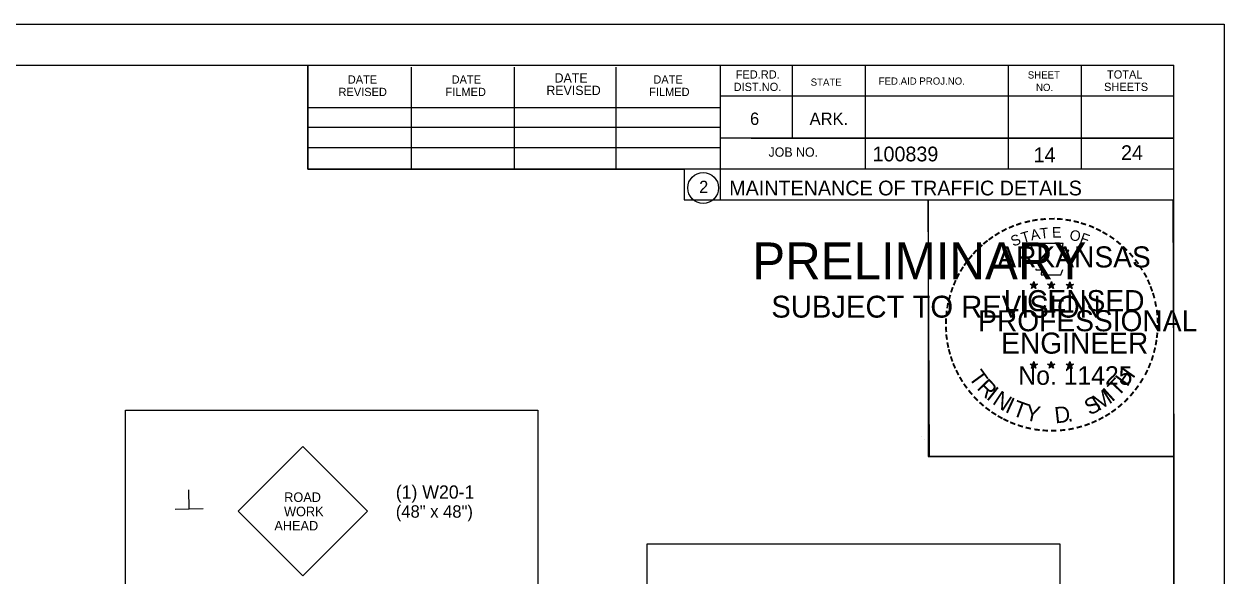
# Model space of a CAD drawing. Extents: x 9792 to 14027, y 9583 to 10649.
# Drawn here: x 10889 to 11459, y 10387 to 10649 of the extents above; entities that cross this region are included whole.
import ezdxf

# ---------------------------------------------------------------- set-up
doc = ezdxf.new("R2010")
doc.units = 0
for name, color, linetype in [('Default', 7, 'Continuous'), ('R_Border', 7, 'Continuous'), ('R_Border Notes', 7, 'Continuous'), ('R_Border PE', 7, 'Continuous'), ('R_Border Prem', 7, 'Continuous'), ('R_Draft', 7, 'Continuous'), ('R_No Plot', 7, 'Continuous')]:
    doc.layers.add(name, color=color, linetype=linetype)

msp = doc.modelspace()

# ---------------------------------------------------------------- linework, layer by layer
at = {"layer": 'Default'}
for p, q in [((11021.52, 10448.84), (10990.87, 10418.19)), ((11052.17, 10418.19), (11021.52, 10448.84)), ((10967.6, 10419.31), (10967.45, 10428.34)), ((10974.19, 10419.23), (10960.95, 10419.01)), ((11021.52, 10387.56), (10990.87, 10418.19)), ((11052.17, 10418.19), (11021.52, 10387.56))]:
    msp.add_line(p, q, dxfattribs=at)
at = {"layer": 'R_Border'}
for p, q in [((9854.26, 10629.85), (11435.16, 10629.85)), ((11023.86, 10580.45), (11023.86, 10629.85)), ((11073.16, 10580.45), (11073.16, 10628.85)), ((11121.96, 10580.45), (11121.96, 10628.85)), ((11170.36, 10580.45), (11170.36, 10628.85)), ((11219.66, 10629.85), (11219.66, 10565.85)), ((11253.86, 10629.85), (11253.86, 10595.15)), ((11288.56, 10629.85), (11288.56, 10580.45)), ((11356.46, 10629.85), (11356.46, 10580.45)), ((11391.16, 10629.85), (11391.16, 10580.45)), ((11435.16, 9602.55), (11435.16, 10629.85)), ((11435.16, 10615.15), (11219.66, 10615.15)), ((11435.16, 10615.25), (11435.16, 10615.25)), ((11023.86, 10609.75), (11219.66, 10609.75)), ((11023.86, 10600.45), (11219.66, 10600.45)), ((11435.16, 10595.15), (11219.66, 10595.15)), ((11234.46, 10595.15), (11435.16, 10595.15)), ((11023.86, 10580.45), (11023.86, 10590.75)), ((11023.86, 10590.75), (11219.66, 10590.75)), ((11435.16, 10580.45), (11023.86, 10580.45)), ((11219.66, 10565.85), (11435.16, 10565.85))]:
    msp.add_line(p, q, dxfattribs=at)
msp.add_circle((11211.6, 10571.53), 7.33, dxfattribs=at)
at = {"layer": 'R_Border Notes'}
for points in [[(10937.26, 10466.18), (11133.09, 10466.18), (11133.09, 10231.02), (10937.26, 10231.02)], [(11185.08, 10402.65), (11380.91, 10402.65), (11380.91, 10252.35), (11185.08, 10252.35)]]:
    msp.add_lwpolyline(points, close=True, dxfattribs=at)
at = {"layer": 'R_Border PE'}
for p, q in [((11366.84, 10525.86), (11368.59, 10525.31)), ((11366.84, 10525.86), (11368.11, 10525.64)), ((11366.84, 10525.86), (11368.03, 10525.25)), ((11367.51, 10523.82), (11368.59, 10525.31)), ((11367.51, 10523.82), (11368.14, 10525.04)), ((11367.51, 10523.82), (11368.58, 10524.91)), ((11368.59, 10527.13), (11368.38, 10525.87)), ((11369.65, 10523.82), (11368.58, 10524.89)), ((11368.59, 10525.31), (11368.59, 10527.13)), ((11368.59, 10527.13), (11368.83, 10525.88)), ((11370.32, 10525.86), (11368.59, 10525.31)), ((11369.65, 10523.82), (11368.59, 10525.31)), ((11370.32, 10525.86), (11368.89, 10525.62)), ((11369.65, 10523.82), (11368.97, 10525.28)), ((11370.32, 10525.86), (11369.3, 10525.35)), ((11375.19, 10525.86), (11376.94, 10525.31)), ((11375.19, 10525.86), (11376.46, 10525.64)), ((11375.19, 10525.86), (11376.38, 10525.25)), ((11375.86, 10523.82), (11376.94, 10525.31)), ((11375.86, 10523.82), (11376.49, 10525.04)), ((11375.86, 10523.82), (11376.93, 10524.91)), ((11376.94, 10527.13), (11376.73, 10525.87)), ((11378, 10523.82), (11376.93, 10524.89)), ((11376.94, 10525.31), (11376.94, 10527.13)), ((11376.94, 10527.13), (11377.18, 10525.88)), ((11378.67, 10525.86), (11376.94, 10525.31)), ((11378, 10523.82), (11376.94, 10525.31)), ((11378.67, 10525.86), (11377.24, 10525.62)), ((11378, 10523.82), (11377.32, 10525.28)), ((11378.67, 10525.86), (11377.65, 10525.35)), ((11384.01, 10525.8), (11385.76, 10525.25)), ((11384.01, 10525.8), (11385.28, 10525.58)), ((11384.01, 10525.8), (11385.2, 10525.19)), ((11384.68, 10523.76), (11385.76, 10525.25)), ((11384.68, 10523.76), (11385.31, 10524.98)), ((11384.68, 10523.76), (11385.75, 10524.85)), ((11385.76, 10527.07), (11385.55, 10525.81)), ((11386.82, 10523.76), (11385.75, 10524.83)), ((11385.76, 10525.25), (11385.76, 10527.07)), ((11385.76, 10527.07), (11386, 10525.82)), ((11387.49, 10525.8), (11385.76, 10525.25)), ((11386.82, 10523.76), (11385.76, 10525.25)), ((11387.49, 10525.8), (11386.06, 10525.56)), ((11386.82, 10523.76), (11386.14, 10525.22)), ((11387.49, 10525.8), (11386.47, 10525.29)), ((11366.82, 10488), (11368.57, 10487.44)), ((11366.82, 10488), (11368.09, 10487.77)), ((11366.82, 10488), (11368.01, 10487.39)), ((11367.49, 10485.96), (11368.57, 10487.44)), ((11367.49, 10485.96), (11368.12, 10487.18)), ((11367.49, 10485.96), (11368.56, 10487.04)), ((11368.57, 10489.27), (11368.36, 10488.01)), ((11369.63, 10485.96), (11368.56, 10487.03)), ((11368.57, 10487.44), (11368.57, 10489.27)), ((11368.57, 10489.27), (11368.81, 10488.02)), ((11370.3, 10488), (11368.57, 10487.44)), ((11369.63, 10485.96), (11368.57, 10487.44)), ((11370.3, 10488), (11368.87, 10487.75)), ((11369.63, 10485.96), (11368.95, 10487.41)), ((11370.3, 10488), (11369.28, 10487.49)), ((11375.17, 10488), (11376.91, 10487.44)), ((11375.17, 10488), (11376.43, 10487.77)), ((11375.17, 10488), (11376.35, 10487.39)), ((11375.83, 10485.96), (11376.91, 10487.44)), ((11375.83, 10485.96), (11376.46, 10487.18)), ((11375.83, 10485.96), (11376.9, 10487.04)), ((11376.91, 10489.27), (11376.71, 10488.01)), ((11377.98, 10485.96), (11376.9, 10487.03)), ((11376.91, 10487.44), (11376.91, 10489.27)), ((11376.91, 10489.27), (11377.16, 10488.02)), ((11378.65, 10488), (11376.91, 10487.44)), ((11377.98, 10485.96), (11376.91, 10487.44)), ((11378.65, 10488), (11377.22, 10487.75)), ((11377.98, 10485.96), (11377.29, 10487.41)), ((11378.65, 10488), (11377.63, 10487.49)), ((11384, 10487.95), (11385.75, 10487.39)), ((11384, 10487.95), (11385.27, 10487.72)), ((11384, 10487.95), (11385.19, 10487.34)), ((11384.67, 10485.91), (11385.75, 10487.39)), ((11384.67, 10485.91), (11385.3, 10487.13)), ((11384.67, 10485.91), (11385.74, 10486.99)), ((11385.75, 10489.22), (11385.54, 10487.96)), ((11386.81, 10485.91), (11385.74, 10486.98)), ((11385.75, 10487.39), (11385.75, 10489.22)), ((11385.75, 10489.22), (11385.99, 10487.97)), ((11387.48, 10487.95), (11385.75, 10487.39)), ((11386.81, 10485.91), (11385.75, 10487.39)), ((11387.48, 10487.95), (11386.05, 10487.7)), ((11386.81, 10485.91), (11386.13, 10487.36)), ((11387.48, 10487.95), (11386.46, 10487.44))]:
    msp.add_line(p, q, dxfattribs=at)
for points in [[(11367.05, 10545.25), (11368.39, 10541.12)], [(11384.6, 10540.64), (11385.31, 10542.06), (11381.89, 10541.94), (11382.63, 10545.25), (11367.05, 10545.25)], [(11369.51, 10533.14), (11369.51, 10532.7), (11372.32, 10532.61), (11372.05, 10530.24), (11381.4, 10530.24), (11382.41, 10532.92)], [(11368.59, 10527.13), (11369.65, 10523.82), (11366.84, 10525.86), (11370.32, 10525.86), (11367.51, 10523.82), (11368.59, 10527.13)], [(11376.94, 10527.13), (11378, 10523.82), (11375.19, 10525.86), (11378.67, 10525.86), (11375.86, 10523.82), (11376.94, 10527.13)], [(11385.76, 10527.07), (11386.82, 10523.76), (11384.01, 10525.8), (11387.49, 10525.8), (11384.68, 10523.76), (11385.76, 10527.07)], [(11368.57, 10489.27), (11369.63, 10485.96), (11366.82, 10488), (11370.3, 10488), (11367.49, 10485.96), (11368.57, 10489.27)], [(11376.91, 10489.27), (11377.98, 10485.96), (11375.17, 10488), (11378.65, 10488), (11375.83, 10485.96), (11376.91, 10489.27)], [(11385.75, 10489.22), (11386.81, 10485.91), (11384, 10487.95), (11387.48, 10487.95), (11384.67, 10485.91), (11385.75, 10489.22)]]:
    msp.add_lwpolyline(points, dxfattribs=at)
for centre, radius in [((11368.58, 10525.31), 0.861), ((11368.58, 10525.31), 0.723), ((11368.58, 10525.31), 0.579), ((11368.58, 10525.31), 0.495), ((11368.58, 10525.31), 0.374), ((11368.58, 10525.31), 0.248), ((11368.58, 10525.31), 0.148), ((11376.93, 10525.31), 0.861), ((11376.93, 10525.31), 0.723), ((11376.93, 10525.31), 0.579), ((11376.93, 10525.31), 0.495), ((11376.93, 10525.31), 0.374), ((11376.93, 10525.31), 0.248), ((11376.93, 10525.31), 0.148), ((11385.75, 10525.25), 0.861), ((11385.75, 10525.25), 0.723), ((11385.75, 10525.25), 0.579), ((11385.75, 10525.25), 0.495), ((11385.75, 10525.25), 0.374), ((11385.75, 10525.25), 0.248), ((11385.75, 10525.25), 0.148), ((11368.56, 10487.44), 0.861), ((11368.56, 10487.44), 0.723), ((11368.56, 10487.44), 0.579), ((11368.56, 10487.44), 0.495), ((11368.56, 10487.44), 0.374), ((11368.56, 10487.44), 0.248), ((11368.56, 10487.44), 0.148), ((11376.91, 10487.44), 0.861), ((11376.91, 10487.44), 0.723), ((11376.91, 10487.44), 0.579), ((11376.91, 10487.44), 0.495), ((11376.91, 10487.44), 0.374), ((11376.91, 10487.44), 0.248), ((11376.91, 10487.44), 0.148), ((11385.74, 10487.39), 0.861), ((11385.74, 10487.39), 0.723), ((11385.74, 10487.39), 0.579), ((11385.74, 10487.39), 0.495), ((11385.74, 10487.39), 0.374), ((11385.74, 10487.39), 0.248), ((11385.74, 10487.39), 0.148)]:
    msp.add_circle(centre, radius, dxfattribs=at)
at = {"layer": 'R_No Plot'}
for p, q in [((9792.26, 10649.32), (11458.93, 10649.32)), ((11315.33, 10453.57), (11315.33, 10453.57)), ((11316.59, 10452.31), (11316.59, 10452.31))]:
    msp.add_line(p, q, dxfattribs=at)
for points in [[(9792.23, 10649.32), (11458.93, 10649.32), (11458.93, 9582.63), (9792.23, 9582.63)], [(11023.86, 10629.85), (11023.86, 10580.45), (11202.52, 10580.45), (11202.52, 10565.85), (11318.52, 10565.85), (11318.52, 10444.19), (11435.16, 10444.19), (11435.16, 9602.55), (9854.26, 9602.55), (9854.26, 10629.85)], [(11318.52, 10565.85), (11434.56, 10565.85), (11435.16, 10444.19), (11319.12, 10444.19)]]:
    msp.add_lwpolyline(points, close=True, dxfattribs=at)

# ---------------------------------------------------------------- texts
at = {"layer": 'Default'}
for s, height, p in [('(1) W20-1', 6.273, (11065.66, 10424.12)), ('(48" x 48")', 5.88, (11065.66, 10415.09))]:
    msp.add_text(s, height=height, dxfattribs=at).set_placement(p)
for s, height, rotation, p in [('ROAD', 4.516, 0.0004, (11012.67, 10422.56)), ('WORK', 4.515, 0, (11012.58, 10415.78)), (' AHEAD ', 4.516, 0.0006, (11006.32, 10409.01))]:
    msp.add_text(s, height=height, rotation=rotation, dxfattribs=at).set_placement(p)
at = {"layer": 'R_Border'}
for s, height, p in [('FED.RD.', 3.91, (11227.06, 10623.45)), ('TOTAL', 3.91, (11403.36, 10623.45)), ('DATE', 3.91, (11042.86, 10621.05)), ('DATE', 3.91, (11092.16, 10621.05)), ('DATE', 4.396, (11141.06, 10621.55)), ('DATE', 3.91, (11187.96, 10621.05)), ('DIST.NO.', 3.91, (11226.06, 10617.55)), ('STATE', 3.42, (11262.66, 10620.05)), ('FED.AID PROJ.NO.', 3.42, (11294.96, 10620.55)), ('SHEET', 3.42, (11365.76, 10623.45)), ('SHEETS', 3.91, (11401.96, 10617.55)), ('REVISED', 3.91, (11038.46, 10615.15)), ('FILMED', 3.91, (11089.26, 10615.15)), ('REVISED', 4.396, (11137.16, 10615.65)), ('FILMED', 3.91, (11185.96, 10615.15)), ('NO.', 3.42, (11369.66, 10617.55)), ('6', 5.86, (11233.86, 10601.45)), ('ARK.', 5.861, (11262.16, 10601.45)), ('JOB NO.', 4.396, (11242.66, 10586.35)), ('100839', 7, (11292.04, 10584.15)), ('2', 5.86, (11209.68, 10569.1)), ('MAINTENANCE OF TRAFFIC DETAILS', 7, (11223.98, 10568))]:
    msp.add_text(s, height=height, dxfattribs=at).set_placement(p)
at = {"layer": 'R_Border PE'}
for s, height, rotation, p in [('-', 8, 24.3072, (11357.62, 10549.54)), ('-', 8, 19.1761, (11360.79, 10550.89)), ('-', 8, 13.6301, (11364.54, 10552.09)), ('-', 8, 10.2193, (11367.93, 10552.9)), ('-', 8, 5.8968, (11371.57, 10553.45)), ('-', 8, 0.1862, (11375.43, 10553.81)), ('-', 8, 357.743, (11379.05, 10553.75)), ('-', 8, 352.1617, (11382.77, 10553.47)), ('-', 8, 347.2049, (11386.36, 10552.9)), ('-', 8, 342.3362, (11389.54, 10552.12)), ('-', 8, 337.8551, (11393.21, 10551.01)), ('-', 8, 36.2317, (11348.58, 10544.13)), ('-', 8, 34.0636, (11351.47, 10546.11)), ('-', 8, 28.7918, (11354.45, 10547.96)), ('S', 5, 21.594, (11358.82, 10543.64)), ('T', 5, 16.4036, (11363.39, 10545.3)), ('A', 5, 11.2132, (11367.52, 10546.55)), ('T', 5, 6.0228, (11371.77, 10547.38)), ('E', 5, 0.8323, (11377.29, 10547.93)), ('O', 5, 350.4515, (11385.31, 10546.88)), ('F', 5, 340.0707, (11390.08, 10545.74)), ('-', 8, 334.1211, (11396.37, 10549.65)), ('-', 8, 329.6409, (11399.26, 10548.24)), ('-', 8, 325.8627, (11402.48, 10546.43)), ('-', 8, 48.423, (11341.79, 10537.77)), ('-', 8, 42.9622, (11344.03, 10540.16)), ('-', 8, 38.9507, (11346.2, 10542.24)), ('ARKANSAS', 10, 360, (11351.31, 10533.81)), ('-', 8, 320.5297, (11405.53, 10544.3)), ('-', 8, 315.5786, (11408.52, 10541.86)), ('-', 8, 54.2325, (11337.71, 10532.5)), ('-', 8, 50.6142, (11339.78, 10535.34)), ('-', 8, 309.8797, (11411.37, 10539.11)), ('-', 8, 306.6522, (11413.99, 10536.1)), ('-', 8, 62.8713, (11334.52, 10526.8)), ('-', 8, 58.0706, (11336.09, 10529.87)), ('-', 7, 303.6753, (11416.42, 10533.26)), ('-', 8, 299.6684, (11418.02, 10530.23)), ('-', 8, 72.3945, (11332.13, 10520.59)), ('-', 8, 67.7743, (11333.23, 10523.74)), ('DWB', 0.05, 360, (11368.52, 10525.28)), ('DWB', 0.05, 360, (11376.87, 10525.28)), ('DWB', 0.05, 360, (11385.69, 10525.23)), ('-', 8, 294.6628, (11419.64, 10527.17)), ('-', 8, 290.5728, (11420.92, 10524.28)), ('-', 8, 75.461, (11331.15, 10517.02)), ('LICENSED', 10, 360, (11354.3, 10513.07)), ('-', 8, 285.1233, (11422.09, 10521.38)), ('-', 8, 85.1863, (11330.11, 10510)), ('-', 8, 81.2013, (11330.49, 10513.46)), ('PROFESSIONAL', 10, 360, (11342.18, 10503.55)), ('-', 8, 280.5493, (11423.09, 10517.67)), ('-', 8, 276.5962, (11423.9, 10513.83)), ('-', 8, 89.0622, (11329.98, 10506.5)), ('-', 8, 274.3301, (11424.2, 10510.22)), ('-', 8, 94.1959, (11330.16, 10502.87)), ('-', 8, 98.9479, (11330.52, 10499.54)), ('ENGINEER', 10, 360, (11353.12, 10492.92)), ('-', 8, 263.5172, (11424.28, 10503.73)), ('-', 8, 269.9407, (11424.37, 10507.06)), ('-', 8, 101.7149, (11331.19, 10495.87)), ('-', 8, 260.9953, (11423.92, 10500.46)), ('-', 8, 105.4578, (11332, 10492.9)), ('-', 8, 109.0874, (11333.08, 10489.74)), ('-', 8, 252.8681, (11422.47, 10493.47)), ('-', 8, 255.7626, (11423.37, 10497.07)), ('-', 8, 114.0643, (11334.35, 10486.76)), ('-', 8, 115.7289, (11335.87, 10483.67)), ('T', 7.7, 306.0406, (11337.37, 10481.64)), ('No. 11425', 8.785, 360, (11361.25, 10478.17)), ('DWB', 0.05, 360, (11368.5, 10487.42)), ('DWB', 0.05, 360, (11376.85, 10487.42)), ('DWB', 0.05, 360, (11385.68, 10487.37)), ('H', 7.7, 54.6088, (11412.97, 10476.81)), ('-', 8, 244.6197, (11420.04, 10486.96)), ('-', 8, 247.8887, (11421.35, 10490.11)), ('-', 8, 120.4471, (11337.66, 10480.74)), ('R', 7.7, 314.005, (11341.18, 10476.4)), ('T', 7.7, 46.6444, (11408.52, 10472.1)), ('-', 8, 239.0712, (11418.07, 10483.2)), ('-', 8, 125.8934, (11339.67, 10477.94)), ('-', 8, 130.7181, (11341.98, 10475.18)), ('I', 7.7, 321.9694, (11345.68, 10471.74)), ('N', 7.7, 326.5002, (11348.52, 10469.38)), ('M', 7.7, 32.6563, (11399.29, 10465.47)), ('I', 7.7, 42.1136, (11405.71, 10469.71)), ('-', 8, 231.2538, (11413.91, 10477.11)), ('-', 8, 233.8452, (11416.06, 10479.94)), ('-', 8, 134.2238, (11344.57, 10472.45)), ('-', 8, 138.9338, (11347.19, 10470.13)), ('-', 8, 144.6463, (11349.97, 10468.1)), ('I', 7.7, 335.3603, (11354.56, 10465.45)), ('T', 7.7, 339.8912, (11357.86, 10463.81)), ('Y', 7.7, 347.8556, (11363.95, 10461.58)), ('D', 7.7, 6.3969, (11378.87, 10459.79)), ('S', 7.7, 26.9312, (11395.09, 10463.44)), ('-', 8, 221.0851, (11408.91, 10471.74)), ('-', 8, 225.7653, (11411.52, 10474.29)), ('-', 8, 148.0898, (11352.78, 10466.25)), ('-', 8, 151.5704, (11355.67, 10464.62)), ('-', 8, 154.6002, (11358.28, 10463.39)), ('.', 7.7, 13.7642, (11384.83, 10460.43)), ('-', 8, 207.3568, (11400.7, 10465.72)), ('-', 8, 212.2491, (11403.49, 10467.45)), ('-', 8, 215.7363, (11406.16, 10469.38)), ('-', 8, 158.5612, (11361.4, 10462.12)), ('-', 8, 162.7983, (11364.84, 10461.05)), ('-', 8, 167.5555, (11368.41, 10460.23)), ('-', 8, 173.1155, (11372.27, 10459.68)), ('-', 8, 176.5183, (11376.01, 10459.42)), ('-', 8, 181.5918, (11379.73, 10459.51)), ('-', 8, 185.8167, (11383.78, 10459.89)), ('-', 8, 191.2858, (11387.46, 10460.55)), ('-', 8, 195.4743, (11391.1, 10461.55)), ('-', 8, 200.7184, (11394.49, 10462.76)), ('-', 8, 204.2516, (11397.58, 10464.12))]:
    msp.add_text(s, height=height, rotation=rotation, dxfattribs=at).set_placement(p)
at = {"layer": 'R_Border Prem'}
for s, height, p in [('PRELIMINARY', 17.5, (11234.92, 10528.17)), ('DWB', 0.05, (11238.65, 10537.41)), ('SUBJECT TO REVISION', 10.3756, (11243.96, 10510.02))]:
    msp.add_text(s, height=height, dxfattribs=at).set_placement(p)
at = {"layer": 'R_Draft'}
for s, p in [('14', (11368.5, 10583.75)), ('24', (11410.03, 10584.77))]:
    msp.add_text(s, height=7, dxfattribs=at).set_placement(p)

doc.saveas('drawing.dxf')
